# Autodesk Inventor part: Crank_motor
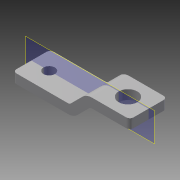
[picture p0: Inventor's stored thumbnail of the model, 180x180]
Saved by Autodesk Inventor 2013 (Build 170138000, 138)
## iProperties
Created: 2006-03
Part Number: Crank_motor
Document SubType Name: Modeling
Designer: debonom
Material: Stainless Steel, 440C
Mass: 46.8106 g
Surface Area: 35.1137 cm^2
Volume: 6.04008 cm^3
Density: 7.75 g/cm^3
Author: debonom
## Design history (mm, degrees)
sketch "Sketch1"
  geometry: L1 (0, 0)-(-22.16, 0); L2 (0, 0)-(9, -9); L3 (9, -9)-(40.46, -9)
  constraints: 6 end point, 1 horizontal, 1 parallel
  dimensions: "d0" = 135 deg angle of L2 L1; "d1" = 62.62 horizontal distance of L3.end L1.end; "d2" = 22.16 distance of L1.start L1.end; "d3" = 9 distance between parallel lines of L3 L1
workplane "Work Plane1"
sketch "Sketch2"
  geometry: L1 (-10, 2.5)-(10, 2.5); L2 (10, 2.5)-(10, -2.5); L3 (10, -2.5)-(-10, -2.5); L4 (-10, -2.5)-(-10, 2.5); L5 (-10, 2.5)-(10, -2.5); 2 further points
  constraints: 10 end point, 2 parallel, 1 coincident, 1 horizontal, 1 midpoint, 1 perpendicular
  dimensions: "d4" = 20 distance of L1.start L1.end; "d5" = 5 distance of L3.end L1.start
sweep "Sweep1" sketch "Sketch2" dims "d6" = 0
fillet "Fillet1" dims "d7" = 7
fillet "Fillet2" dims "d8" = 2
sketch "Sketch3"
  geometry: L1 (-12.524, 10)-(75.144, 10) reference; L2 (0, 20)-(0, 0) reference; C1 r 3.05 at (9.5, 10); 1 further point
  constraints: 1 centre point, 1 point on line
  dimensions: "d9" = 9.5 distance from line of C1.centre L2; "d10" = 6.1 diameter of C1
extrude "Extrusion1" cut sketch "Sketch3" stored distance "d11" = 10; taper "d12" = 0 deg
sketch "Sketch4"
  geometry: L1 (-75.144, 10)-(12.524, 10) reference; L2 (0, 24)-(0, -4) reference; C1 r 5 at (-11, 10); 1 further point
  constraints: 1 centre point, 1 point on line
  dimensions: "d13" = 11 distance from line of C1.centre L2; "d14" = 10 diameter of C1
extrude "Extrusion2" cut sketch "Sketch4" stored distance "d15" = 10; taper "d16" = 0 deg
fillet "Fillet3" dims "d17" = 2
node "Mobile"
body "Solid1"
